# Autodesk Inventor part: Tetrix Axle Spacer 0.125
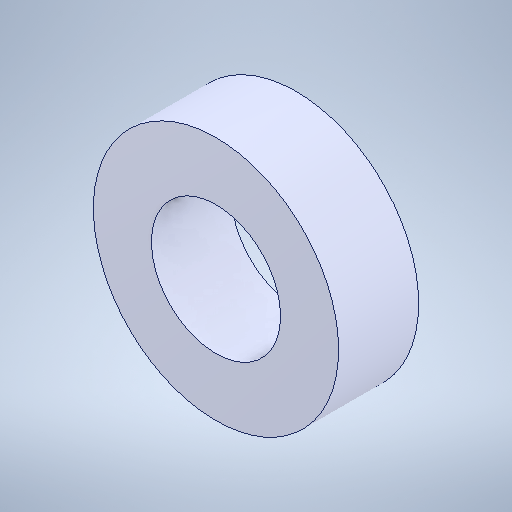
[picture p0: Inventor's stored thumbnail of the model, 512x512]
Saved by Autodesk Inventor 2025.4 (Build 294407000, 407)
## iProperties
Created: 2021-10
Part Number: Tetrix Axle Spacer 0.125
Material: Genérico
Document SubType Name: Modeling
Designer: usuario
Density: 1 g/cm^3
Appearance: Valor por defecto
Author: usuario
Sending System: SolidWorks 2016
Last Author: LENOVO
Last Saved: 2021-10-23
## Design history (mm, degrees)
feature "Revolve1"
node "Plane1"
node "Sólido1"
